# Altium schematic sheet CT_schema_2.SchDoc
size 287 x 169 mm
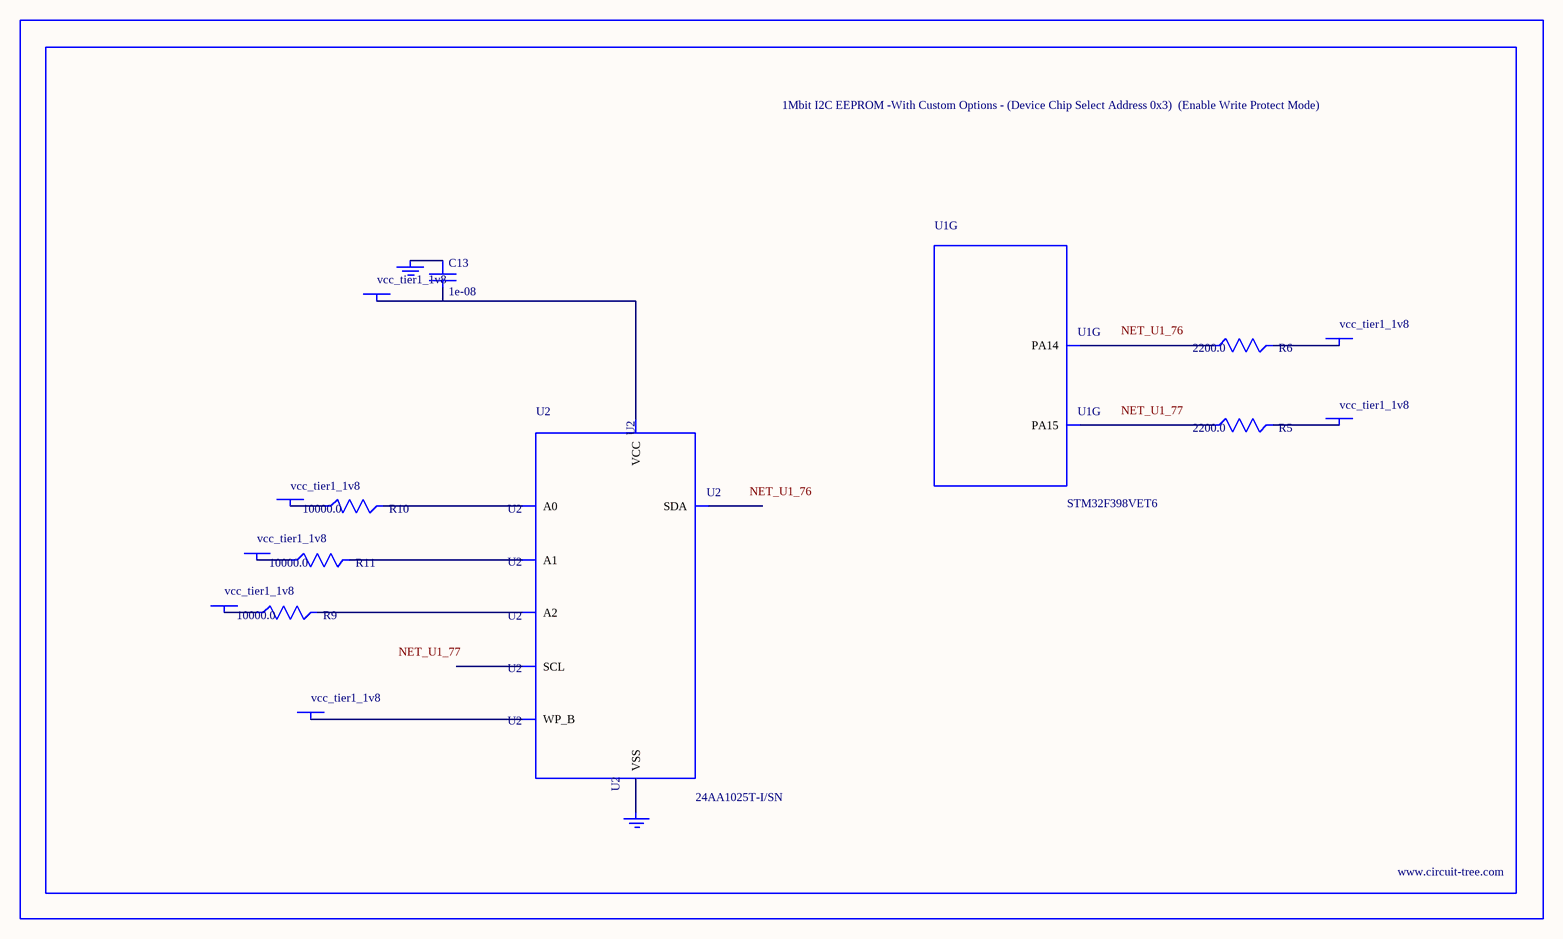
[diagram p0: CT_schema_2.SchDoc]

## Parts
BORDER1  (no value)
C13  1e-08  [C0402]
GND_INSTANCE_1_0  (no value)
GND_INSTANCE_1_1  (no value)
POWER_INSTANCE_1_0  vcc_tier1_1v8
POWER_INSTANCE_1_1  vcc_tier1_1v8
POWER_INSTANCE_1_2  vcc_tier1_1v8
POWER_INSTANCE_1_3  vcc_tier1_1v8
POWER_INSTANCE_1_4  vcc_tier1_1v8
POWER_INSTANCE_1_5  vcc_tier1_1v8
POWER_INSTANCE_1_6  vcc_tier1_1v8
R5  2200.0  [R0603]
R6  2200.0  [R0603]
R9  10000.0  [R0603]
R10  10000.0  [R0603]
R11  10000.0  [R0603]
U1  STM32F398VET6  [LQFP100]  (part G of 8)
U2  24AA1025T-I/SN  [SOIC-8]

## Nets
NetC13_1: C13.1 GND_INSTANCE_1_0.0(GND)
NetC13_2: C13.2 POWER_INSTANCE_1_4.0(PWR) U2.8(VCC)
NetGND_INSTANCE_1_1_0: GND_INSTANCE_1_1.0(GND) U2.4(VSS)
NetPOWER_INSTANCE_1_0_0: POWER_INSTANCE_1_0.0(PWR) R10.1
NetPOWER_INSTANCE_1_1_0: POWER_INSTANCE_1_1.0(PWR) R11.1
NetPOWER_INSTANCE_1_2_0: POWER_INSTANCE_1_2.0(PWR) R9.1
NetPOWER_INSTANCE_1_3_0: POWER_INSTANCE_1_3.0(PWR) U2.7(WP_B)
NetPOWER_INSTANCE_1_5_0: POWER_INSTANCE_1_5.0(PWR) R6.2
NetPOWER_INSTANCE_1_6_0: POWER_INSTANCE_1_6.0(PWR) R5.2
NetR5_1: R5.1 U1.77(PA15)
NetR6_1: R6.1 U1.76(PA14)
NetR9_2: R9.2 U2.3(A2)
NetR10_2: R10.2 U2.1(A0)
NetR11_2: R11.2 U2.2(A1)

Not connected (* = marked no-connect by the designer): U2 5(SDA) 6(SCL)

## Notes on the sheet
- Labels drawn without touching a wire or pin: NET_U1_76, NET_U1_77

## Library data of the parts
BORDER1 = BORDER_PAGE1
C13 = C0402C103K3RAC
GND_INSTANCE_1_0 GND_INSTANCE_1_1 = GND
POWER_INSTANCE_1_0-POWER_INSTANCE_1_6 = PWR
R5 R6 = RC0603JR-072K2L
R9-R11 = RC0603JR-0710KL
